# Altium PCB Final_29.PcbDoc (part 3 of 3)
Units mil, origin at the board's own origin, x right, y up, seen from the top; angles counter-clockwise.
Board outline 11000 x 6000 mil, 4 copper layers (TopLayer, MidLayer1, MidLayer2, BottomLayer), stack 29.222 mil thick; 209 components, 95 nets, 681 pads, 861 vias.
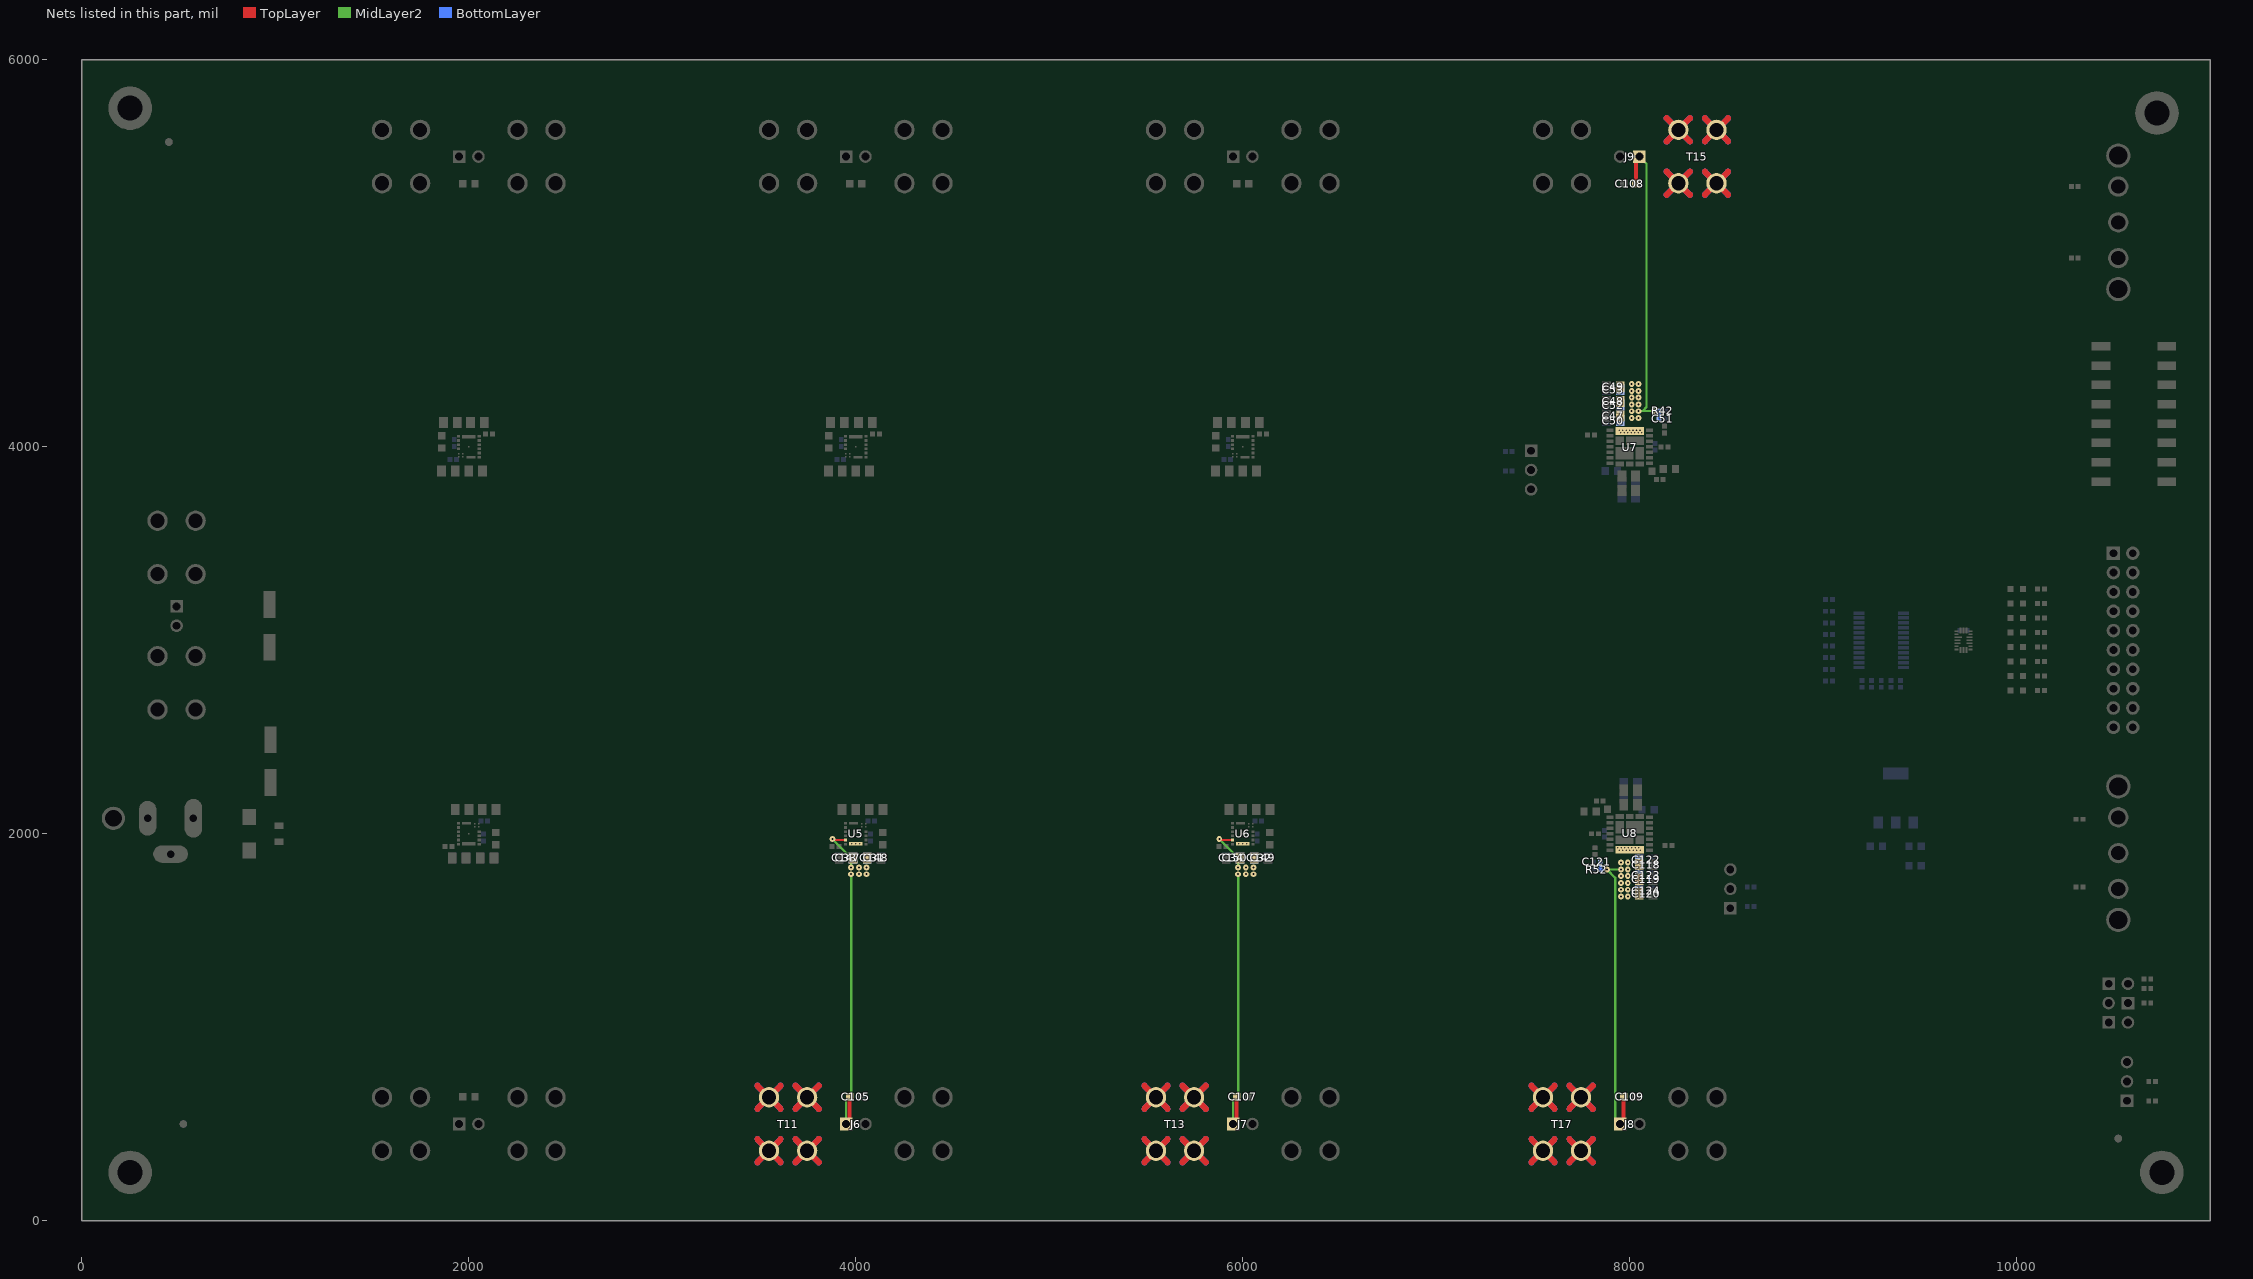
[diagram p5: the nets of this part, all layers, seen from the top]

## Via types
v1: diameter 30, hole 10, TopLayer to BottomLayer, tented both sides, 493 vias
v2: diameter 18, hole 8, TopLayer to BottomLayer, tented both sides, 308 vias
v3: diameter 18, hole 8, TopLayer to BottomLayer, tented bottom, 60 vias

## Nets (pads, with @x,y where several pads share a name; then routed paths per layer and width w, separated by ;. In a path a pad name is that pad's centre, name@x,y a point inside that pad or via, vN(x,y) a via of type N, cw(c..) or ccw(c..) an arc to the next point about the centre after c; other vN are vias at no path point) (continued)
VOUT5: C31.1 C33.1 C105.2 C147.1 C148.1 J6.1 T11.1 T11.2 T11.3 T11.4 U5.5 U5.7 | length 4417.6
  TopLayer w12: v1(3879,1973) 3884.5,1967.5 U5.5@3946.9,1967.5
  TopLayer w20: J6.1@3950,500 3968.5,518.5 C105.2@3968.5,640
  TopLayer w32: 3491.6,302.1 T11.2@3551.5,362 ; 3491.6,421.9 T11.2@3551.5,362 ; 3491.6,578.1 T11.1@3551.5,638 ; 3491.6,697.9 T11.1@3551.5,638 ; 3611.4,302.1 T11.2@3551.5,362 ; 3611.4,421.9 T11.2@3551.5,362 ; 3611.4,578.1 T11.1@3551.5,638 ; 3611.4,697.9 T11.1@3551.5,638 ; 3688.6,302.1 T11.3@3748.5,362 ; 3688.6,421.9 T11.3@3748.5,362 ; 3688.6,578.1 T11.4@3748.5,638 ; 3688.6,697.9 T11.4@3748.5,638 ; 3808.4,302.1 T11.3@3748.5,362 ; 3808.4,421.9 T11.3@3748.5,362 ; 3808.4,578.1 T11.4@3748.5,638 ; 3808.4,697.9 T11.4@3748.5,638
  MidLayer2 w12: v1(3879,1973) 3976,1876 v1(3976,1826) ; J6.1@3950,500 3950,618 3976,644 v1(3976,1791)
  BottomLayer w32: 3491.6,302.1 T11.2@3551.5,362 ; 3491.6,421.9 T11.2@3551.5,362 ; 3491.6,578.1 T11.1@3551.5,638 ; 3491.6,697.9 T11.1@3551.5,638 ; 3611.4,302.1 T11.2@3551.5,362 ; 3611.4,421.9 T11.2@3551.5,362 ; 3611.4,578.1 T11.1@3551.5,638 ; 3611.4,697.9 T11.1@3551.5,638 ; 3688.6,302.1 T11.3@3748.5,362 ; 3688.6,421.9 T11.3@3748.5,362 ; 3688.6,578.1 T11.4@3748.5,638 ; 3688.6,697.9 T11.4@3748.5,638 ; 3808.4,302.1 T11.3@3748.5,362 ; 3808.4,421.9 T11.3@3748.5,362 ; 3808.4,578.1 T11.4@3748.5,638 ; 3808.4,697.9 T11.4@3748.5,638
  other v1: 4016,1791 4056,1791 4016,1826 4056,1826
  other v2: 3979,1948 4000,1947.8 4021,1948
VOUT6: C32.1 C34.1 C107.2 C149.1 C150.1 J7.1 T13.1 T13.2 T13.3 T13.4 U6.5 U6.7 | length 4417.6
  TopLayer w12: v1(5879,1973) 5884.5,1967.5 U6.5@5946.9,1967.5
  TopLayer w20: J7.1@5950,500 5968.5,518.5 C107.2@5968.5,640
  TopLayer w32: 5491.6,302.1 T13.2@5551.5,362 ; 5491.6,421.9 T13.2@5551.5,362 ; 5491.6,578.1 T13.1@5551.5,638 ; 5491.6,697.9 T13.1@5551.5,638 ; 5611.4,302.1 T13.2@5551.5,362 ; 5611.4,421.9 T13.2@5551.5,362 ; 5611.4,578.1 T13.1@5551.5,638 ; 5611.4,697.9 T13.1@5551.5,638 ; 5688.6,302.1 T13.3@5748.5,362 ; 5688.6,421.9 T13.3@5748.5,362 ; 5688.6,578.1 T13.4@5748.5,638 ; 5688.6,697.9 T13.4@5748.5,638 ; 5808.4,302.1 T13.3@5748.5,362 ; 5808.4,421.9 T13.3@5748.5,362 ; 5808.4,578.1 T13.4@5748.5,638 ; 5808.4,697.9 T13.4@5748.5,638
  MidLayer2 w12: v1(5879,1973) 5976,1876 v1(5976,1826) ; J7.1@5950,500 5950,618 5976,644 v1(5976,1791)
  BottomLayer w32: 5491.6,302.1 T13.2@5551.5,362 ; 5491.6,421.9 T13.2@5551.5,362 ; 5491.6,578.1 T13.1@5551.5,638 ; 5491.6,697.9 T13.1@5551.5,638 ; 5611.4,302.1 T13.2@5551.5,362 ; 5611.4,421.9 T13.2@5551.5,362 ; 5611.4,578.1 T13.1@5551.5,638 ; 5611.4,697.9 T13.1@5551.5,638 ; 5688.6,302.1 T13.3@5748.5,362 ; 5688.6,421.9 T13.3@5748.5,362 ; 5688.6,578.1 T13.4@5748.5,638 ; 5688.6,697.9 T13.4@5748.5,638 ; 5808.4,302.1 T13.3@5748.5,362 ; 5808.4,421.9 T13.3@5748.5,362 ; 5808.4,578.1 T13.4@5748.5,638 ; 5808.4,697.9 T13.4@5748.5,638
  other v1: 6016,1791 6056,1791 6016,1826 6056,1826
  other v2: 5979,1948 6000,1947.8 6021,1948
VOUT7: C47.1 C48.1 C49.1 C50.1 C51.1 C52.1 C53.1 C108.2 J9.1 R42.1 T15.1 T15.2 T15.3 T15.4 U7.8 | length 4344.8
  TopLayer w20: C108.2@8031.5,5360 8031.5,5481.5 J9.1@8050,5500
  TopLayer w32: 8191.6,5302.1 T15.2@8251.5,5362 ; 8191.6,5421.9 T15.2@8251.5,5362 ; 8191.6,5578.1 T15.1@8251.5,5638 ; 8191.6,5697.9 T15.1@8251.5,5638 ; 8311.4,5302.1 T15.2@8251.5,5362 ; 8311.4,5421.9 T15.2@8251.5,5362 ; 8311.4,5578.1 T15.1@8251.5,5638 ; 8311.4,5697.9 T15.1@8251.5,5638 ; 8388.6,5302.1 T15.3@8448.5,5362 ; 8388.6,5421.9 T15.3@8448.5,5362 ; 8388.6,5578.1 T15.4@8448.5,5638 ; 8388.6,5697.9 T15.4@8448.5,5638 ; 8508.4,5302.1 T15.3@8448.5,5362 ; 8508.4,5421.9 T15.3@8448.5,5362 ; 8508.4,5578.1 T15.4@8448.5,5638 ; 8508.4,5697.9 T15.4@8448.5,5638
  MidLayer2 w12: v1(8045,4184) 8046,4185 8067,4185 ; J9.1@8050,5500 8087,5463 8087,4205 8067,4185 ; v1(8124,4185) 8067,4185
  BottomLayer w12: v1(8124,4185) R42.1@8152.3,4185 C51.1@8152.3,4145
  BottomLayer w32: 8191.6,5302.1 T15.2@8251.5,5362 ; 8191.6,5421.9 T15.2@8251.5,5362 ; 8191.6,5578.1 T15.1@8251.5,5638 ; 8191.6,5697.9 T15.1@8251.5,5638 ; 8311.4,5302.1 T15.2@8251.5,5362 ; 8311.4,5421.9 T15.2@8251.5,5362 ; 8311.4,5578.1 T15.1@8251.5,5638 ; 8311.4,5697.9 T15.1@8251.5,5638 ; 8388.6,5302.1 T15.3@8448.5,5362 ; 8388.6,5421.9 T15.3@8448.5,5362 ; 8388.6,5578.1 T15.4@8448.5,5638 ; 8388.6,5697.9 T15.4@8448.5,5638 ; 8508.4,5302.1 T15.3@8448.5,5362 ; 8508.4,5421.9 T15.3@8448.5,5362 ; 8508.4,5578.1 T15.4@8448.5,5638 ; 8508.4,5697.9 T15.4@8448.5,5638
  other v1: 8010,4149 8045,4149 8010,4184 8010,4219 8045,4219 8010,4254 8045,4254 8010,4289 8045,4289 8010,4324 8045,4324
  other v2: 7954,4073 7972,4073 7990,4073 8008,4073 8026,4073 8044,4073 8062,4073 7945,4086 7963,4086 7981,4086 7999,4086 8017,4086 8035,4086 8053,4086
VOUT8: C109.2 C118.1 C119.1 C120.1 C121.1 C122.1 C123.1 C124.1 J8.1 R52.1 T17.1 T17.2 T17.3 T17.4 U8.8 | length 4349.3
  TopLayer w20: J8.1@7950,500 7968.5,518.5 C109.2@7968.5,640
  TopLayer w32: 7491.6,302.1 T17.2@7551.5,362 ; 7491.6,421.9 T17.2@7551.5,362 ; 7491.6,578.1 T17.1@7551.5,638 ; 7491.6,697.9 T17.1@7551.5,638 ; 7611.4,302.1 T17.2@7551.5,362 ; 7611.4,421.9 T17.2@7551.5,362 ; 7611.4,578.1 T17.1@7551.5,638 ; 7611.4,697.9 T17.1@7551.5,638 ; 7688.6,302.1 T17.3@7748.5,362 ; 7688.6,421.9 T17.3@7748.5,362 ; 7688.6,578.1 T17.4@7748.5,638 ; 7688.6,697.9 T17.4@7748.5,638 ; 7808.4,302.1 T17.3@7748.5,362 ; 7808.4,421.9 T17.3@7748.5,362 ; 7808.4,578.1 T17.4@7748.5,638 ; 7808.4,697.9 T17.4@7748.5,638
  MidLayer2 w12: J8.1@7950,500 7925,525 7925,1772 v1(7882,1815) 7954,1815 v1(7955,1816)
  BottomLayer w12: C121.1@7847.7,1855 R52.1@7847.7,1815 v1(7882,1815)
  BottomLayer w32: 7491.6,302.1 T17.2@7551.5,362 ; 7491.6,421.9 T17.2@7551.5,362 ; 7491.6,578.1 T17.1@7551.5,638 ; 7491.6,697.9 T17.1@7551.5,638 ; 7611.4,302.1 T17.2@7551.5,362 ; 7611.4,421.9 T17.2@7551.5,362 ; 7611.4,578.1 T17.1@7551.5,638 ; 7611.4,697.9 T17.1@7551.5,638 ; 7688.6,302.1 T17.3@7748.5,362 ; 7688.6,421.9 T17.3@7748.5,362 ; 7688.6,578.1 T17.4@7748.5,638 ; 7688.6,697.9 T17.4@7748.5,638 ; 7808.4,302.1 T17.3@7748.5,362 ; 7808.4,421.9 T17.3@7748.5,362 ; 7808.4,578.1 T17.4@7748.5,638 ; 7808.4,697.9 T17.4@7748.5,638
  other v1: 7955,1676 7990,1676 7955,1711 7990,1711 7955,1746 7990,1746 7955,1781 7990,1781 7990,1816 7955,1851 7990,1851
  other v2: 7947,1914 7965,1914 7983,1914 8001,1914 8019,1914 8037,1914 8055,1914 7938,1927 7956,1927 7974,1927 7992,1927 8010,1927 8028,1927 8046,1927
pads on no net: J18.0 SW1.SH1 SW1.SH2 SW2.SH1 SW2.SH2 U1.15 U2.15 U3.15 U4.15 U5.15 U6.15 U7.1 U8.1
copper on no net: | length 93.2
  TopLayer w12: 7885,2127 7897.6,2114.4 7897.6,2085.6 ; 8102.4,3914.4 8102.4,3885.6 8115,3873

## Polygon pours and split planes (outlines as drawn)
3.3V on TopLayer "3.3V_1" (solid, remove dead copper, pour order 95): 77 vertices, not listed, extent 8840,917 10737,3540
N1133411 on TopLayer "N1133411_1" (solid, remove dead copper, pour order 88): 8208,2108 8178,2078 8091,2078 8091,2091 8153,2153 8208,2153
N983153 on TopLayer "N983153_1" (solid, remove dead copper, pour order 76): 7983,3895 7983,3922 8018,3922 8018,3895
N983255 on TopLayer "N983255_1" (solid, remove dead copper, pour order 77): 7792,3892 7822,3922 7909,3922 7909,3909 7847,3847 7792,3847
PGND on TopLayer "PGND_1" (solid, remove dead copper, pour order 87): 10614.7,1190.3 ccw(c10574.96,1224.93) 10624.6,1207.2 10625.8,1210.5 10634.3,1210.5 10634.3,1187.2 ccw(c10644.49,1187.25) 10634.8,1184.1 cw(c10625.29,1181) 10625.3,1171 10622.5,1171 10621.1,1172.3 ccw(c10607.64,1157.39) 10617.3,1175 cw(c10622.22,1183.71)
PGND on TopLayer "PGND_2" (solid, remove dead copper, pour order 64): 95 vertices, not listed, extent 54,51 1955.6,5947
PGND on TopLayer "PGND_3" (solid, remove dead copper, pour order 112): 69 vertices, not listed, extent 2013,53 3953,2336
PGND on TopLayer "PGND_4" (solid, remove dead copper, pour order 66): 67 vertices, not listed, extent 4014,3664 5955.7,5948
PGND on TopLayer "PGND_5" (solid, remove dead copper, pour order 86): 176 vertices, not listed, extent 7982,52 10948,2792
PGND on TopLayer "PGND_6" (solid, remove dead copper, pour order 85): 10620.7,1277.9 10660.5,1277.9 cw(c10660.43,1267.91) 10670.1,1265.4 ccw(c10679.92,1262.95) 10669.8,1262.8 10669.8,1237.2 ccw(c10679.91,1237.1) 10670,1235.1 cw(c10660.23,1232.99) 10660.2,1223 10644.5,1223 ccw(c10644.61,1212.82) 10640.9,1222.3 cw(c10637.35,1231.66) 10627.4,1230.6 ccw(c10575,1225.01) 10613.4,1261.1 cw(c10620.73,1267.9)
PGND on TopLayer "PGND_7" (solid, remove dead copper, pour order 84): 10616.5,872 10697.6,872 10697.6,743 10669.5,743 ccw(c10669.5,732.85) 10661,738.4 10659.5,736.1 10620.3,736.1 10619,739.3 ccw(c10569.97,720.02) 10601.8,762 cw(c10607.83,770) 10601.8,778 ccw(c10570.05,820) 10622.7,820 ccw(c10570.09,820) 10609.1,855.3 cw(c10616.53,862)
PGND on TopLayer "PGND_8" (solid, remove dead copper, pour order 98): 66 vertices, not listed, extent 2014,3664 3955.7,5948
PGND on TopLayer "PGND_9" (solid, remove dead copper, pour order 99): 96 vertices, not listed, extent 6014,3664 8018,5948
PGND on TopLayer "PGND_10" (solid, remove dead copper, pour order 100): 71 vertices, not listed, extent 4013,53 5953,2336
PGND on TopLayer "PGND_11" (solid, remove dead copper, pour order 101): 46 vertices, not listed, extent 6013,53 7782,2336
PGND on TopLayer "PGND_12" (solid, remove dead copper, pour order 103): 49 vertices, not listed, extent 8218,3340 10948,5949
PVIN on TopLayer "PVIN_1" (solid, remove dead copper, pour order 96): 212 vertices, not listed, extent 264,1788 9280,3999
VOUT1 on TopLayer "VOUT1_1" (solid, remove dead copper, pour order 97): 18 vertices, not listed, extent 1015,4043.4 2038,5948
VOUT2 on TopLayer "VOUT2_1" (solid, remove dead copper, pour order 108): 18 vertices, not listed, extent 3015,4043.4 4038,5948
VOUT3 on TopLayer "VOUT3_1" (solid, remove dead copper, pour order 109): 18 vertices, not listed, extent 5015,4043.4 6038,5948
VOUT4 on TopLayer "VOUT4_1" (solid, remove dead copper, pour order 65): 19 vertices, not listed, extent 1058,52 2087,1956.6
VOUT5 on TopLayer "VOUT5_1" (solid, remove dead copper, pour order 110): 19 vertices, not listed, extent 3015,52 4087,1956.6
VOUT6 on TopLayer "VOUT6_1" (solid, remove dead copper, pour order 111): 19 vertices, not listed, extent 5015,52 6087,1956.6
VOUT7 on TopLayer "VOUT7_1" (solid, remove dead copper, pour order 102): 19 vertices, not listed, extent 7926.2,4062 8810,5948
VOUT8 on TopLayer "VOUT8_1" (solid, remove dead copper, pour order 104): 34 vertices, not listed, extent 7015,52 8073.8,1937
3.3V on BottomLayer "3.3V_2" (solid, remove dead copper, pour order 94): 9487,2009 9440,2009 9440,2093 9627,2093 9627,1813 9487,1813
N1133327 on BottomLayer "N1133327_1" (solid, remove dead copper, pour order 83): 8021,2077 8019,2075 7982,2075 7982,2145 8081,2145 8081,2106 8021,2106
N1133411 on BottomLayer "N1133411_2" (solid, remove dead copper, pour order 89): 8193,2085 8106,2085 8106,2145 8193,2145
N983153 on BottomLayer "N983153_2" (solid, remove dead copper, pour order 78): 7979,3923 7981,3925 8018,3925 8018,3855 7919,3855 7919,3894 7979,3894
N983255 on BottomLayer "N983255_2" (solid, remove dead copper, pour order 82): 7805,3915 7894,3915 7894,3855 7805,3855
PGND on BottomLayer "PGND_14" (solid, remove dead copper, pour order 121): 9711.3,3103.9 9858.3,3103.9 9864.8,3097.4 9864.8,3095.3 ccw(c9890.01,3094.97) 9876.8,3073.5 cw(c9871.59,3065) 9876.8,3056.5 ccw(c9890.04,3035.06) 9865.2,3039.3 9864.5,3035.1 9730.2,3035.1 9730.2,3062.8 ccw(c9720.1,3062.8) 9720.1,3072.9 9708.9,3072.9 9704.2,3077.6 9704.2,3079.7 ccw(c9678.97,3080.15) 9702.2,3090 cw(c9711.37,3093.92)
PGND on BottomLayer "PGND_15" (solid, remove dead copper, pour order 120): 9596.2,2938.4 9843.8,2938.4 9864.8,2917.4 9864.8,2915.3 ccw(c9890.02,2914.79) 9865.4,2909.3 cw(c9855.67,2907.08) 9855.7,2897.1 9575.1,2897.1 cw(c9575.07,2907.1) 9565.1,2907.9 ccw(c9540.01,2910.15) 9565.2,2910 ccw(c9540.03,2909.61) 9565,2912.8 cw(c9574.95,2913.89) 9575,2923.9 ccw(c9575,2940.08) 9586.4,2928.6
PGND on BottomLayer "PGND_16" (solid, remove dead copper, pour order 119): 224 vertices, not listed, extent 51,50 10950,5949
PVIN on BottomLayer "PVIN_2" (solid, remove dead copper, pour order 67): 5978,2240 6092,2240 6092,2092 6074,2092 6074,2026 6029,2026 6022,2033 6022,2079 5978,2079
PVIN on BottomLayer "PVIN_3" (solid, remove dead copper, pour order 68): 1978,2240 2092,2240 2092,2092 2074,2092 2074,2026 2022,2026 2022,2079 1978,2079
PVIN on BottomLayer "PVIN_4" (solid, remove dead copper, pour order 69): 3978,2240 4092,2240 4092,2092 4074,2092 4074,2026 4022,2026 4022,2079 3978,2079
PVIN on BottomLayer "PVIN_5" (solid, remove dead copper, pour order 70): 6022,3760 5908,3760 5908,3908 5926,3908 5926,3974 5974,3974 5978,3970 5978,3921 6022,3921
PVIN on BottomLayer "PVIN_6" (solid, remove dead copper, pour order 71): 4022,3760 3908,3760 3908,3908 3926,3908 3926,3974 3978,3974 3978,3921 4022,3921
PVIN on BottomLayer "PVIN_7" (solid, remove dead copper, pour order 75): 2022,3760 1908,3760 1908,3908 1926,3908 1926,3974 1978,3974 1978,3921 2022,3921
PVIN on BottomLayer "PVIN_8" (solid, remove dead copper, pour order 91): 7850,2316 7993,2316 7993,2150.1 7976.9,2150.1 7976.9,2150 7968,2150 7968,1990 7892.9,1990 7892.9,2005.2 7887.9,2005.2 7887.9,2035.6 7874.9,2035.6 7866.7,2043.8 7857.1,2043.8 ccw(c7837.71,2027.69) 7850,2049.7
PVIN on BottomLayer "PVIN_9" (solid, remove dead copper, pour order 80): 8083.1,4015 8112.1,4015 8112.1,3964.4 8125.1,3964.4 8133.3,3956.2 8142.9,3956.2 ccw(c8162.29,3972.31) 8150,3950.3 8150,3684 8007,3684 8007,3844 8032,3844 8032,4014.9 8083.1,4014.9
PVIN on BottomLayer "PVIN_10" (solid, remove dead copper, pour order 93): 9263,1862 9126,1862 9126,2092 9310,2092 9310,2014 9263,2014
VOUT1 on BottomLayer "VOUT1_2" (solid, remove dead copper, pour order 115): 17 vertices, not listed, extent 1015,4043 2039,5948
VOUT2 on BottomLayer "VOUT2_2" (solid, remove dead copper, pour order 116): 3849,5311 3986,5311 3986,5010 4039,5010 4039,4056 4026,4043 3975,4043 3921,4097 3917,4097 3917,4315 3015,4315 3015,5948 3986,5948 3986,5616 3849,5616
VOUT3 on BottomLayer "VOUT3_2" (solid, remove dead copper, pour order 117): 17 vertices, not listed, extent 5015,4043 6039,5948
VOUT4 on BottomLayer "VOUT4_2" (solid, remove dead copper, pour order 113): 17 vertices, not listed, extent 1058,52 2088,1957
VOUT5 on BottomLayer "VOUT5_2" (solid, remove dead copper, pour order 72): 17 vertices, not listed, extent 3015,52 4088,1957
VOUT6 on BottomLayer "VOUT6_2" (solid, remove dead copper, pour order 73): 6029,1957 6088,1898 6088,988 5986,988 5986,695 5860,695 5860,410 5984,410 5984,52 5015,52 5015,1711 5960,1711 5960,1943 5974,1957
VOUT7 on BottomLayer "VOUT7_2" (solid, remove dead copper, pour order 118): 22 vertices, not listed, extent 7928,4063 8810,5948
VOUT8 on BottomLayer "VOUT8_2" (solid, remove dead copper, pour order 114): 29 vertices, not listed, extent 7015,52 8072,1937
AGND1 on BottomLayer "AGND1_1" (solid, remove dead copper, pour order 79): 8000,4020 8000,4042 8078,4042 8078,4020
AGND2 on BottomLayer "AGND2_1" (solid, remove dead copper, pour order 92): 8000,1980 8000,1958 7922,1958 7922,1980
PGND on MidLayer2 "PGND_26" (solid, remove dead copper, pour order 122): 50,50 50,5950 10950,5950 10950,50
PGND on MidLayer2 "PGND_17" (solid, remove dead copper, pour order 131): 21 vertices, not listed, extent 9564.97,3201.2 10448.6,3281.9
PGND on MidLayer2 "PGND_18" (solid, remove dead copper, pour order 130): 19 vertices, not listed, extent 9898.44,3021.1 10468.17,3133.9
PGND on MidLayer2 "PGND_19" (solid, remove dead copper, pour order 129): 23 vertices, not listed, extent 9548.44,3021.1 9881.56,3109.9
PGND on MidLayer2 "PGND_20" (solid, remove dead copper, pour order 128): 18 vertices, not listed, extent 9898.44,2871.06 10468.17,2988.9
PGND on MidLayer2 "PGND_21" (solid, remove dead copper, pour order 127): 9574.1,2988.9 9855,2988.9 cw(c9855.05,2978.89) 9865,2977.8 ccw(c9889.97,2974.61) 9864.8,2975 ccw(c9890.06,2975) 9876.8,2953.5 cw(c9871.59,2945) 9876.8,2936.5 ccw(c9890.06,2915) 9864.8,2915 ccw(c9889.99,2915.15) 9864.9,2912.9 cw(c9854.93,2912.1) 9854.9,2902.1 9630.7,2902.1 9565.2,2967.6 9565.2,2969.7 ccw(c9539.99,2970.09) 9564.4,2976.4 cw(c9574.07,2978.91)
PGND on MidLayer2 "PGND_22" (solid, remove dead copper, pour order 126): 23 vertices, not listed, extent 9565.2,2725.94 10447.95,2857
PGND on MidLayer2 "PGND_23" (solid, remove dead copper, pour order 125): 10041,2838.9 10445.8,2838.9 10446.8,2835.2 ccw(c10499.95,2850.1) 10455.7,2817.1 cw(c10447.69,2811.1) 10447.7,2801.1 10054.7,2801.1 10033.9,2821.8 cw(c10040.98,2828.88)
PGND on MidLayer2 "PGND_24" (solid, remove dead copper, pour order 124): 22 vertices, not listed, extent 8301.7,636.1 10542.15,2014.9
PGND on MidLayer2 "PGND_25" (solid, remove dead copper, pour order 123): 18 vertices, not listed, extent 9914.1,3142.1 10468.17,3210.9
VOUT1 on MidLayer2 "VOUT1_3" (solid, remove dead copper, pour order 74): 1968,4181.7 1968,4201.3 1968.2,4202 ccw(c1944,4209.03) 1969.2,4209 ccw(c1944,4208.97) 1968.2,4216 1968,4216.7 1968,4225 2041,4225 2041,4156 1968,4156 1968,4166.3 1968.2,4167 ccw(c1944,4174.03) 1969.2,4174 ccw(c1944,4173.97) 1968.2,4181
VOUT2 on MidLayer2 "VOUT2_3" (solid, remove dead copper, pour order 61): 3968,4181.7 3968,4201.3 3968.2,4202 ccw(c3944,4209.03) 3969.2,4209 ccw(c3944,4208.97) 3968.2,4216 3968,4216.7 3968,4225 4041,4225 4041,4156 3968,4156 3968,4166.3 3968.2,4167 ccw(c3944,4174.03) 3969.2,4174 ccw(c3944,4173.97) 3968.2,4181
VOUT3 on MidLayer2 "VOUT3_3" (solid, remove dead copper, pour order 63): 5968,4181.7 5968,4201.3 5968.2,4202 ccw(c5944,4209.03) 5969.2,4209 ccw(c5944,4208.97) 5968.2,4216 5968,4216.7 5968,4225 6041,4225 6041,4156 5968,4156 5968,4166.3 5968.2,4167 ccw(c5944,4174.03) 5969.2,4174 ccw(c5944,4173.97) 5968.2,4181
VOUT4 on MidLayer2 "VOUT4_3" (solid, remove dead copper, pour order 62): 2032,1818.3 2032,1798.7 2031.8,1798 ccw(c2056,1790.97) 2030.8,1791 ccw(c2056,1791.03) 2031.8,1784 2032,1783.3 2032,1775 1959,1775 1959,1844 2032,1844 2032,1833.7 2031.8,1833 ccw(c2056,1825.97) 2030.8,1826 ccw(c2056,1826.03) 2031.8,1819
VOUT5 on MidLayer2 "VOUT5_3" (solid, remove dead copper, pour order 60): 4032,1818.3 4032,1798.7 4031.8,1798 ccw(c4056,1790.97) 4030.8,1791 ccw(c4056,1791.03) 4031.8,1784 4032,1783.3 4032,1775 3959,1775 3959,1844 4032,1844 4032,1833.7 4031.8,1833 ccw(c4056,1825.97) 4030.8,1826 ccw(c4056,1826.03) 4031.8,1819
VOUT6 on MidLayer2 "VOUT6_3" (solid, remove dead copper, pour order 59): 6032,1818.3 6032,1798.7 6031.8,1798 ccw(c6056,1790.97) 6030.8,1791 ccw(c6056,1791.03) 6031.8,1784 6032,1783.3 6032,1775 5959,1775 5959,1844 6032,1844 6032,1833.7 6031.8,1833 ccw(c6056,1825.97) 6030.8,1826 ccw(c6056,1826.03) 6031.8,1819
AGND1 on MidLayer2 "AGND1_2" (solid, remove dead copper, pour order 81): 77 vertices, not listed, extent 7266,3696 8337,4379
AGND2 on MidLayer2 "AGND2_2" (solid, remove dead copper, pour order 90): 92 vertices, not listed, extent 7663,1581 8719,1983
PGND on MidLayer1 "PGND_13" (solid, remove dead copper, pour order 107): 51,5949 10948,5949 10948,52 51,52

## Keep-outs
TopLayer:
  region: 10479,425 ccw(c10525,425) 10571,425 ccw(c10525,425)
  region: 479,500 ccw(c525,500) 571,500 ccw(c525,500)
  region: 404,5575 ccw(c450,5575) 496,5575 ccw(c450,5575)
BottomLayer:
  region: 10571,425 cw(c10525,425) 10479,425 cw(c10525,425)
  region: 571,500 cw(c525,500) 479,500 cw(c525,500)
  region: 496,5575 cw(c450,5575) 404,5575 cw(c450,5575)
KeepOutLayer:
  region: 117.6,250 ccw(c250,250) 382.4,250 ccw(c250,250)
  region: 117.6,5750 ccw(c250,5750) 382.4,5750 ccw(c250,5750)
  region: 10617.6,250 ccw(c10750,250) 10882.4,250 ccw(c10750,250)
  region: 10592.6,5725 ccw(c10725,5725) 10857.4,5725 ccw(c10725,5725)
  region: 10515,1200 10515,1150 10535,1150 10535,1200
  region: 10550,2925 10550,2885 10560,2885 10560,2925
  region: 10545,3025 10545,2985 10565,2985 10565,3025

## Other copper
TopLayer:
  text "COMPONENT-SIDE" at 3394,-675 h73.5
  text "1" at 6569,-675 h73.5
MidLayer1:
  rectangle net AGND2: 7926,1947 8005,1985
  rectangle net AGND1: 7997,4017 8079,4053
  region net PGND: 7864,1909 7885,1928 7926,1960 7931,1949 7894,1905 7873,1896
  region net PGND: 8127,4102 8108,4095 8072,4052 8078.83,4041.7 8136,4090
  text "2" at 6569,-675 h73.5
  text "GROUND PLANE" at 3420.5,-679.5 h73.5
MidLayer2:
  text "3" at 5891.5,-654.5 h73.5
  text "3" at 6591.5,-654.5 h73.5
  text "INTERNAL SIGNAL" at 3420.5,-679.5 h73.5
BottomLayer:
  text "SOLDER-SIDE" at 3394,-675 h73.5
  text "4" at 6569,-675 h73.5

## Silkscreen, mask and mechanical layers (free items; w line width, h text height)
TopOverlay:
  region: 6145,2955 6145,2770 8375,2770 8375,2955
  region: 7960,3250 7960,3045 8375,3045 8375,3250
  lines w8: 1705,4325 1815,4325 ; 1785,4295 1815,4325 ; 1785,4350 1810,4325 1815,4325 ; 1815,3980 1815,3825 2130,3825 2130,3955 ; 1815,4070 1815,4175 1855,4175 ; 1815,4200 1815,4370 ; 1865,1895 1865,1815 2195,1815 2195,1935 ; 1865,2070 1865,2180 1885,2180 ; 2100,4175 2130,4175 2130,4110 ; 2130,4190 2130,4370 ; 2145,3825 2430,3825 ; 2155,4175 2430,4175 ; 2160,4295 2135,4320 2130,4320 ; 2160,4350 2130,4320 ; 2190,2180 2195,2180 2195,2030 ; 2240,4320 2130,4320 ; 2335,3860 2365,3830 2365,3825 ; 2335,4145 2360,4170 2360,4175 ; 2360,4065 2360,4175 ; 2365,3980 2365,3825 ; 2390,4145 2360,4175 ; 2400,3860 2365,3825 ; 3815,3980 3815,3825 4130,3825 4130,3955 ; 3815,4070 3815,4175 3830,4175 ; 3865,1895 3865,1815 4195,1815 4195,1935 ; 3865,2070 3865,2180 3885,2180 ; 4120,4175 4130,4175 4130,4110 ; 4190,2180 4195,2180 4195,2030 ; 5815,3980 5815,3825 6130,3825 6130,3955 ; 5815,4070 5815,4175 5835,4175 ; 5865,1895 5865,1815 6195,1815 6195,1935 ; 5865,2070 5865,2180 5885,2180 ; 6130,4110 6130,4180 ; 6190,2180 6195,2180 6195,2030 ; 7635,4530 7745,4530 ; 7715,4500 7745,4530 ; 7715,4555 7740,4530 7745,4530 ; 7745,1853 7745,1650 8280,1650 ; 7745,2164 7745,2305 8280,2305 8280,2002 ; 7745,3960 7745,3710 8280,3710 8280,3760 ; 7745,4345 7745,4365 8280,4365 8280,4145 ; 7745,4380 7745,4565 ; 8280,4385 8280,4565 ; 8290,4365 8605,4365 ; 8295,3710 8605,3710 8605,3705 ; 8315,4505 8290,4530 8285,4530 ; 8315,4560 8285,4530 ; 8395,4530 8285,4530 ; 8470,3745 8500,3715 ; 8475,4330 8500,4355 8500,4360 ; 8500,3960 8500,3715 ; 8500,4100 8500,4360 ; 8525,3745 8500,3720 8500,3715 ; 8530,4330 8500,4360
  text "GND" at 10724.87,5323.3 h49
  text "VOUT7" at 8156.08,5158 h78.4
  text "PGND" at 2194.07,5153 h78.4
  text "PGND" at 4194.07,5153 h78.4
  text "PGND" at 6194.07,5153 h78.4
  text "VOUT1" at 1441.08,5148 h78.4
  text "VOUT2" at 3441.08,5148 h78.4
  text "VOUT3" at 5441.08,5148 h78.4
  text "PGND" at 7499.07,5143 h78.4
  text "3.3V" at 10717.34,4963.3 h49
  text "13.5mm" at 7917.28,4510 h49
  text "EN1" at 10184.87,4495 h49
  text "EN2" at 10184.87,4395 h49
  text "8mm" at 1919.87,4305 h49
  text "EN3" at 10184.87,4295 h49
  text "EN4" at 10184.87,4195 h49
  text "EN5" at 10184.87,4095 h49
  text "16.6mm" at 8497.28,4025 h49
  text "8.9mm" at 2324.81,4000 h49
  text "EN6" at 10184.87,3995 h49
  text "SYNC" at 7265.34,3959 h49
  text "EN7" at 10184.87,3895 h49
  text "SALERT" at 7198.28,3852 h49
  text "EN8" at 10184.87,3795 h49
  text "PVIN" at 650.07,3449 h78.4
  text "POWER MICRO BOARD REV" at 5952.86,3075 h98
  text "S/N" at 5780.07,2811.7 h98
  text "uPOL" at 4372.67,2805 h196
  text "PGND" at 658.07,2730 h78.4
  text "GND" at 10739.87,2063.3 h49
  text "3.3V" at 10732.34,1703.3 h49
  text "SALERT" at 8636.28,1696 h49
  text "SYNC" at 8614.34,1591 h49
  text "GND" at 10379.87,800 h49
  text "PGND" at 2172.07,757 h78.4
  text "PGND" at 4172.07,757 h78.4
  text "PGND" at 6172.07,757 h78.4
  text "PGND" at 8172.07,757 h78.4
  text "VOUT4" at 1419.08,752 h78.4
  text "VOUT5" at 3419.08,752 h78.4
  text "VOUT6" at 5419.08,752 h78.4
  text "VOUT8" at 7419.08,752 h78.4
  text "SDA" at 10380.87,698 h49
  text "SCL" at 10382.87,586 h49
  text "SILKSCREEN C.S." at 3294,-675 h73.5
  text "7" at 6569,-675 h73.5
BottomOverlay:
  text "SILKSCREEN S.S." at 3294,-675 h73.5
  text "8" at 6569,-675 h73.5
TopPaste:
  drawing of 76 lines, arcs and shapes, not listed
  text "SOLDER PASTE C.S." at 3294,-675 h73.5
  text "9" at 6569,-675 h73.5
BottomPaste:
  text "SOLDER PASTE S.S." at 3294,-675 h73.5
  text "10" at 6569,-675 h73.5
TopSolder:
  drawing of 114 lines, arcs and shapes, not listed
  text "SOLDER MASK C.S." at 3394,-675 h73.5
  text "5" at 6569,-675 h73.5
BottomSolder:
  drawing of 171 lines, arcs and shapes, not listed
  text "SOLDER MASK S.S." at 3394,-675 h73.5
  text "6" at 6569,-675 h73.5
Board_Outline:
  drawing of 172 lines, arcs and shapes, not listed
  text "5" at -6010.08,10706 h122.5
  text "4" at -2045.08,10706 h122.5
  text "3" at 1919.92,10706 h122.5
  text "2" at 5884.92,10706 h122.5
  text "1" at 9849.92,10706 h122.5
  text "REVISIONS" at 8575,10490 h122.5
  text "LTR" at 6263,10240 h98
  text "DESCRIPTION" at 7625,10240 h98
  text "BY" at 9828,10240 h98
  text "DATE" at 10255,10240 h98
  text "APPROVED" at 10850,10240 h98
  text "C" at -8068.08,7805 h122.5
  text "B" at -8068.08,2680 h122.5
  text "UNLESS OTHERWISE SPECIFIED" at 1775,-2185 h98
  text "CONTRACT NO." at 4513.96,-2210 h98
  text "DIMENSIONS ARE IN INCHES" at 1850,-2360 h98
  text "A" at -8068.08,-2420 h122.5
  text "TOLERANCES ON" at 2525,-2610 h98
  text "SIGNATURE" at 4737.67,-2835 h98
  text "TITLE" at 6877.6,-2835 h98
  text "2 PLACES DECIMALS" at 1775,-2860 h98
  text "+.02" at 3553.83,-2870 h98
  text "3 PLACES DECIMALS" at 1775,-3110 h98
  text "+.005" at 3562.6,-3120 h98
  text "+" at 4106.92,-3120 h122.5
  text "PREPARED" at 4425,-3185 h78.4
  text "POWER MICROSTRIP GEN 1" at 7170,-3230 h196
  text "+" at 4175,-3310 h92.12
  text "+1" at 3575,-3335 h92.12
  text "ANGLES" at 1750,-3360 h98
  text "CHECKED" at 4425,-3485 h78.4
  text "DO NOT SCALE THIS DRAWING" at 1825,-3610 h98
  text "ENGINEER" at 4425,-3785 h78.4
  text "MATERIAL" at 1750,-3885 h98
  text "SIZE" at 6868.83,-4035 h98
  text "DRAWING NO." at 7405.2,-4035 h98
  text "REV." at 11293.83,-4035 h98
  text "Q.A." at 4425,-4060 h78.4
  text "PROGRAM" at 4450,-4235 h78.4
  text "MANG." at 4450,-4335 h78.4
  text "C" at 6930.68,-4404 h171.5
  text "NEXT ASSY" at -925,-4460 h98
  text "USED ON" at 625,-4460 h98
  text "FINAL PROTECTIVE FINISH" at 1750,-4460 h98
  text "RELEASE" at 4500,-4610 h78.4
  text "APPLICATION" at -250,-4735 h98
  text "SCALE" at 6877.6,-4735 h98
  text "SHEET" at 9852.6,-4735 h98
  text "OF" at 11126.3,-4735 h98
  text "1" at 11417.53,-4735 h98
  text "DATE" at 4500,-4760 h78.4
PLACE_BOUND_TOP:
  region: 10613,5725 ccw(c10725,5725) 10837,5725 ccw(c10725,5725)
  region: 10638,250 ccw(c10750,250) 10862,250 ccw(c10750,250)
  region: 138,250 ccw(c250,250) 362,250 ccw(c250,250)
  region: 138,5750 ccw(c250,5750) 362,5750 ccw(c250,5750)
DB36:
  drawing of 640 lines, arcs and shapes, not listed
  text "FARADAY SEMI" at 2425,-350 h73.5
  text "PWB." at 4469,-350 h73.5
  text "POWERSTRIP" at 4844,-350 h73.5
  text "DATE:" at 6094,-350 h73.5
  text "10/29/20" at 6569,-350 h73.5
  text "LAYER NAME:" at 2419,-675 h73.5
  text "LAYER NO." at 5094,-675 h73.5
  text "FILM" at 6169,-675 h73.5
  text "OF" at 6794,-675 h73.5
  text "10" at 6994,-675 h73.5
  text "LARGO" at 3943,-1101.2 h98
  text "CIRCUIT" at 4618,-1101.2 h98
  text "DESIGN" at 5463,-1101.2 h98
  text "WWW.LARGO-CD.COM" at 5015,-1229.2 h61.74
  text "(714)898-1588" at 3939,-1230.2 h61.74
  text "DRW.POWERSTRIP" at 5015,-1379.2 h61.74
  text "PROJ.PCB.3579" at 3939,-1380.2 h61.74
  text "LARGO" at 5015,-1504.2 h61.74
  text "REV.01" at 5415,-1504.2 h61.74
  text "C.S.-VIEW" at 3989,-1535.2 h78.4
SPLIT:
  lines w25: 975,1725 2000,1725 ; 1000,3475 1000,6125 ; 1475,2350 11200,2350 ; 1475,3000 11200,3000 ; 1600,3650 8300,3650 ; 2000,375 2000,975 2100,975 2100,1050 ; 2000,5265 2000,5935 ; 2975,1725 4000,1725 ; 3000,-700 3000,4450 ; 3001,5282 3001,5952 ; 4000,5265 4000,5935 ; 5000,-225 5000,4375 ; 5001,5282 5001,5952 ; 6000,5265 6000,5935 ; 6925,1900 7875,1900 ; 7000,-250 7000,3725 ; 7000,3475 7000,6125 ; 7915,4116 7915,5026 8000,5025 8000,6075 ; 8000.5,-81.5 8000.5,968.5 8085.5,967.5 8085.5,1877.5 ; 8075,4125 8824,4125 8826,6072 ; 8150,3800 8825,3800 8825,2350 ; 8525,2175 9050,2175 9050,1775 10100,1775 10100,825 10750,825 10750,1450 ; 8850,3325 10150,3325 10150,3550 10225,3550 10225,5150 10300,5150 10300,5625 11025,5625
PLACE_GRID_TOP:
  lines w0.04: -550,2000 11800,2000 ; -450,4000 10500,4000 ; 2000,-1000 2000,9600 ; 4000,-1000 4000,9600 ; 6000,-700 6000,9900 ; 8000,-1000 8000,9600
DIMENSION:
  lines w0.04: -1243,0 -100,0 ; -1050,0 -100,0 ; -1050,6000 -100,6000 ; -950,3418 -950,0 ; -950,3932 -950,6000 ; -550,0 -100,0 ; -550,250 150,250 ; -450,-300 -450,0 ; -450,1468 -450,250 ; -300,-300 0,-300 ; 0,-1043 0,-100 ; 0,-825 0,-100 ; 0,-400 0,-100 ; 250,-400 250,150 ; 718,-300 250,-300 ; 990,6475 1210,6475 1891.1,4090 ; 2645,6475 2925,6475 3905,4090 ; 3760,-1125 3405,-1125 2111.7,1900 ; 4715,6480 4945,6480 5897,4090 ; 4968,-725 0,-725 ; 5240,-1145 4820,-1140 4101.1,1900 ; 6432,-725 11000,-725 ; 7915,-1185 7540,-1170 6077.4,1900 ; 9055,6480 8605,6475 8100,4106.2 ; 9805,-1175 9360,-1175 8052.2,1885 ; 11000,-825 11000,-100 ; -7280,-3420 -7230,-3570 ; -7280,-3420 -7180,-3420 ; -7280,-3420 -7230,-3570 ; -7280,-3420 -7180,-3420 ; -7280,-2470 -7230,-2320 ; -7280,-2470 -7180,-2470 ; -7280,-2470 -7230,-2320 ; -7280,-2470 -7180,-2470 ; -7230,-3570 -7180,-3420 ; -7230,-3570 -7230,-3270 -7230,-3570 ; -7230,-3570 -7180,-3420 ; -7230,-2320 -7230,-2645 -7230,-2320 ; -7230,-2320 -7180,-2470 ; -7230,-2320 -7180,-2470 ; -950,0 -975,150 -925,150 -950,0 ; -950,6000 -925,5850 -975,5850 -950,6000 ; -450,0 -425,-150 -475,-150 -450,0 ; -450,250 -475,400 -425,400 -450,250 ; 0,-725 150,-700 150,-750 0,-725 ; 0,-300 -150,-325 -150,-275 0,-300 ; 250,-300 400,-275 400,-325 250,-300 ; 1891.1,4090 1825.9,4227.4 1873.9,4241.1 1891.1,4090 ; 2111.7,1900 2193.7,1771.9 2147.7,1752.2 2111.7,1900 ; 3905,4090 3824.9,4219.2 3871.1,4238.2 3905,4090 ; 4101.1,1900 4159.9,1759.8 4111.3,1748.3 4101.1,1900 ; 5897,4090 5818.3,4220.1 5864.7,4238.6 5897,4090 ; 6077.4,1900 6164.5,1775.3 6119.3,1753.8 6077.4,1900 ; 8052.2,1885 8134.1,1756.9 8088.2,1737.2 8052.2,1885 ; 8100,4106.2 8106.8,4258.1 8155.7,4247.7 8100,4106.2 ; 11000,-725 10850,-750 10850,-700 11000,-725 ; -7765,4865 -7470,4865 -7470,5120 -7765,5120 -7765,4865 ; -7760.5,4290.5 -7465.5,4290.5 -7465.5,4545.5 -7760.5,4545.5 -7760.5,4290.5 ; -7730,-3570 -6580,-3570 -7730,-3570 ; -7730,-2320 -6580,-2320 -7730,-2320 ; 0,0 11000,0 11000,6000 0,6000 0,0 ; 1865,3880 2060,3880 2060,4090 1865,4090 1865,3880 ; 1940,1900 2135,1900 2135,2125 1940,2125 1940,1900 ; 3865,3880 4060,3880 4060,4090 3865,4090 3865,3880 ; 3940,1900 4135,1900 4135,2125 3940,2125 3940,1900 ; 5865,3880 6060,3880 6060,4090 5865,4090 5865,3880 ; 5940,1900 6135,1900 6135,2125 5940,2125 5940,1900 ; 7785,3845 8100,3845 8100,4110 7785,4110 7785,3845 ; 7880,1885 8205,1885 8205,2145 7880,2145 7880,1885
  text "18" at 802.22,6437.5 h73.5
  text "18" at 4527.22,6437.5 h73.5
  text "18" at 9042.22,6432.5 h73.5
  text "18" at 2462.22,6427.5 h73.5
  text "6.000" at -1425,3575 h196
  text "17" at -7107.78,1627.5 h73.5
  text "18" at -6907.78,1627.5 h73.5
  text ".250" at -825,1625 h196
  text "17" at -6902.78,1442.5 h73.5
  text "0" at -1550,-100 h196
  text ".250" at 875,-400 h196
  text "11.000" at 5125,-825 h196
  text "18" at 3757.22,-1157.5 h73.5
  text "18" at 5232.22,-1172.5 h73.5
  text "18" at 9797.22,-1207.5 h73.5
  text "18" at 7907.22,-1217.5 h73.5
  text "0" at -75,-1400 h196
TOOLING_CORNERS:
  lines w8: -4,-4 -4,396 -4,-4 ; -4,-4 396,-4 -4,-4 ; -4,6004 396,6004 -4,6004 ; -4,6004 -4,5604 -4,6004 ; 11004,-4 10604,-4 11004,-4 ; 11004,-4 11004,396 11004,-4 ; 11004,6004 11004,5604 11004,6004 ; 11004,6004 10604,6004 11004,6004
  lines w35: -50,-50 -50,496 -50,-50 ; -50,-50 496,-50 -50,-50 ; -50,6050 496,6050 -50,6050 ; -50,6050 -50,5504 -50,6050 ; 11050,-50 10504,-50 11050,-50 ; 11050,-50 11050,496 11050,-50 ; 11050,6050 11050,5504 11050,6050 ; 11050,6050 10504,6050 11050,6050
TITLE_DATA:
  text "FABRICATION DRAWING" at 7625,-3560 h196
  text "1:1" at 7672,-4763 h152.88
TITLE_BLOCK:
  text "ASSEMBLY DRAWING" at 7625,-3560 h196
  text ".75:1" at 7560,-4765 h152.88
FAB_NOTES:
  drawing of 155 lines, arcs and shapes, not listed
  text "UNLESS OTHERWISE SPECIFIED:" at -7744,10423 h122.5
  text "1. USE ARTWORK MASTERS SUPPLIED." at -7744,10173 h98
  text "2. BOARD SHALL BE VERIFIED FOR COMPLIANCE WITH THE SUPPLIED IPC-D-356 NETLIST." at -7744,9973 h98
  text "3. DRAWING IS VIEWED FROM COMPONENT SIDE." at -7744,9773 h98
  text "4. ALL DIMENSIONS ARE IN INCHES." at -7744,9573 h98
  text "5. FINISHED BOARD SHALL MEET THE PERFORMANCE REQUIREMENTS OF IPC-6012 B, CLASS 2." at -7744,9373 h98
  text "6. MATERIAL:" at -7744,9173 h98
  text "BASE LAMINATE:  PLASTIC SHEET, GLASS BASE EPOXY RESIN, NEMA FR4" at -7744,8973 h98
  text "OR EQUIVALENT, UL94-V0." at -7744,8773 h98
  text "BONDING AGENT:  PREIMPREGNATED B-STAGE EPOXY GLASS CLOTH." at -7744,8573 h98
  text "7. BOARD BOW, WARP OR TWIST SHALL NOT EXCEED +/- 0.0075 PER INCH MEASURED" at -7744,8373 h98
  text "IN ACCORDANCE WITH IPC-TM-650, METHOD 2.4.22." at -7744,8173 h98
  text "8. HOLE SIZE SHALL BE PER HOLE LEGEND." at -7744,7973 h98
  text "9. DRILL BOARD USING DRILL DATA SUPPLIED. HOLE LOCATIONS MAY VARY" at -7744,7773 h98
  text "WITHIN 0.003 (RADIAL ERROR) MAX, ABOUT TRUE POSITION." at -7744,7573 h98
  text "10. REGISTRATION: FRONT TO BACK GRID REGISTRATION ON HOLE CENTERS" at -7744,7373 h98
  text "TO BE WITHIN 0.005." at -7744,7173 h98
  text "11. COPPER PLATE INDICATED HOLES, 0.001 MINIMUM WALL THICKNESS," at -7744,6973 h98
  text "12. TOTAL CIRCUIT ETCH ACROSS TRACES SHALL BE +/- 0.001 OF THE" at -7744,6773 h98
  text "SUPPLIED ARTWORK." at -7744,6573 h98
  text "13. SOLDER MASK OVER BARE COPPER BOTH SIDES USING LIQUID PHOTO-IMAGEABLE" at -7744,6373 h98
  text "SOLDERMASK PER IPC-SM-840." at -7744,6173 h98
  text "14. FINISH: SOLDER PLATE OVER EXPOSED CONDUCTORS, 0.0003 MIN THK," at -7744,5973 h98
  text "COMP SN60." at -7744,5773 h98
  text "15. SILKSCREEN BOTH SIDES WITH NONCONDUCTIVE CONTRASTING EPOXY INK" at -7744,5573 h98
  text "USING ARTWORK SUPPLIED." at -7744,5373 h98
  text "16. REMOVE ALL BURRS AND BREAK SHARP EDGES 0.015 INCH MAXIMUM." at -7744,5173 h98
  text "17. ALL 0.008 AND 0.010 VIA DRILLS (EXCEPT AS NOTED IN NOTE 18)" at -7744,4973 h98
  text "SHALL BE PLUGGED WITH LPI SOLDERMASK PRIOR TO APPLYING" at -7744,4773 h98
  text "THE COMPONENT AND SOLDER SIDE SOLDER MASKS." at -7744,4573 h98
  text "18. INDICATED VIAS SHALL BE COPPER FILLED." at -7744,4373 h98
  text "LAYER STACKUP" at -5480,-1820 h152.88
  text "COPPER WEIGHT SHOWN IS AFTER PLATING" at -6230,-2070 h98
  text "COMPONENT SIDE SILKSCREEN" at -3330,-2220 h78.4
  text "COMPONENT SIDE SOLDERMASK" at -3330,-2370 h78.4
  text "LAYER 1      COMPONENT SIDE         2.0 OZ" at -6430,-2545 h78.4
  text "0.063 +/-.010" at -7780,-2845 h78.4
  text "LAYER 2      GROUND PLANE           2.0 OZ" at -6430,-2845 h78.4
  text "INCLUDING" at -7580,-2995 h78.4
  text "FR-4 0.034" at -5180,-2995 h78.4
  text "SOLDERMASK" at -7605,-3145 h78.4
  text "LAYER 3      INTERNAL SIGNAL        2.0 OZ" at -6430,-3145 h78.4
  text "FR-4 0.008" at -5180,-3295 h78.4
  text "LAYER 4      SOLDER SIDE            2.0 OZ" at -6430,-3445 h78.4
  text "SOLDER SIDE SOLDERMASK" at -3330,-3620 h78.4
  text "SOLDER SIDE SILKSCREEN" at -3330,-3770 h78.4
LOGO:
  drawing of 294 lines, arcs and shapes, not listed
ASSYDWG:
  drawing of 4099 lines, arcs and shapes, not listed
  text "J2" at -5812.6,5635 h49
  text "J3" at -4312.6,5635 h49
  text "J4" at -2812.6,5635 h49
  text "J9" at -1322.6,5630 h49
  text "R18" at 294.87,5440 h49
  text "C102" at -5837.66,5400 h49
  text "C108" at -1342.66,5395 h49
  text "C103" at -4342.66,5390 h49
  text "C104" at -2837.66,5390 h49
  text "T3" at -6070.1,5366.2 h49
  text "T4" at -5545.1,5366.2 h49
  text "T5" at -4580.1,5361.2 h49
  text "T6" at -4055.1,5361.2 h49
  text "T7" at -3075.1,5361.2 h49
  text "T8" at -2550.1,5361.2 h49
  text "T18" at -1582.63,5356.2 h49
  text "T15" at -1057.63,5356.2 h49
  text "SW1" at 379.87,5280 h49
  text "R74" at 284.87,5150 h49
  text "ON" at 792.4,4880 h49
  text "1" at 588.64,4815 h49
  text "2" at 588.64,4740 h49
  text "C49" at -1265.13,4670 h49
  text "3" at 588.64,4665 h49
  text "C53" at 4738.67,4642.5 h49
  text "C48" at -1265.13,4605 h49
  text "4" at 588.64,4590 h49
  text "R42" at 4314.87,4590 h49
  text "C10" at -4425.13,4585 h49
  text "C16" at -2925.13,4585 h49
  text "C17" at -2765.13,4585 h49
  text "C141" at 7452.34,4585 h49
  text "C139" at 8957.34,4585 h49
  text "C140" at 9157.34,4585 h49
  text "C52" at 4738.67,4582.5 h49
  text "C4" at -5892.6,4580 h49
  text "C11" at -4255.13,4580 h49
  text "C144" at 5962.34,4580 h49
  text "C143" at 6167.34,4580 h49
  text "C142" at 7662.34,4580 h49
  text "C5" at -5772.6,4575 h49
  text "C47" at -1260.13,4540 h49
  text "C51" at 4314.87,4530 h49
  text "C50" at 4738.67,4522.5 h49
  text "SW3" at 369.87,4520 h49
  text "5" at 588.64,4515 h49
  text "C44" at -1105.13,4495 h49
  text "R44" at 4494.87,4490 h49
  text "1" at -1680.06,4485 h49
  text "R3" at -5657.6,4480 h49
  text "R6" at -4157.6,4480 h49
  text "R9" at -2657.6,4480 h49
  text "R39" at -1575.13,4470 h49
  text "C3" at -5987.6,4450 h49
  text "C15" at -3025.13,4450 h49
  text "C9" at -4482.6,4445 h49
  text "C133" at 6202.34,4445 h49
  text "C132" at 7707.34,4445 h49
  text "6" at 588.64,4440 h49
  text "C134" at 9207.34,4440 h49
  text "C45" at -1085.13,4430 h49
  text "R36" at 4369.87,4425 h49
  text "U1" at -5702.6,4420 h49
  text "U3" at -2692.6,4415 h49
  text "U2" at -4187.6,4410 h49
  text "R54" at 5119.87,4410 h49
  text "U7" at -1457.6,4395 h49
  text "R4" at 7697.4,4370 h49
  text "R1" at 9207.4,4370 h49
  text "7" at 588.64,4365 h49
  text "R7" at 6202.4,4365 h49
  text "C43" at -1055.13,4345 h49
  text "J17" at -1820.13,4335 h49
  text "C42" at 4729.87,4330 h49
  text "R31" at 5119.87,4330 h49
  text "C38" at -1455.13,4315 h49
  text "8" at 588.64,4290 h49
  text "C40" at 4428.67,4290 h49
  text "C1" at -5882.6,4270 h49
  text "C2" at -5782.6,4270 h49
  text "C8" at -4392.6,4270 h49
  text "C7" at -4277.6,4270 h49
  text "C14" at -2925.13,4270 h49
  text "C13" at -2765.13,4270 h49
  text "C39" at -1450.13,4250 h49
  text "R27" at -1190.13,4250 h49
  text "C41" at 4428.67,4233.7 h49
  text "T1" at -6947.6,4210 h49
  text "3" at -1685.06,4180 h49
  text "1" at 531.14,4082.5 h49
  text "2" at 643.64,4082.5 h49
  text "R73" at 366.57,3875.2 h49
  text "PG8" at 109.91,3872.5 h37.24
  text "R63" at 3874.91,3840 h37.24
  text "R72" at 366.57,3819 h49
  text "PG7" at 109.91,3816.2 h37.24
  text "C101" at -6420,3807.66 h49 r270
  text "R62" at 3874.91,3795 h37.24
  text "POWER MICRO BOARD REV" at -2952.75,3792.7 h73.5
  text "J1" at -6862.6,3770 h49
  text "U11" at -30.13,3765 h49
  text "C151" at 3257.34,3765 h49
  text "U10" at 3605,3765.13 h49 r270
  text "R71" at 366.57,3762.7 h49
  text "PG6" at 109.91,3760 h37.24
  text "R61" at 3874.91,3745 h37.24
  text "R70" at 366.57,3706.5 h49
  text "PG5" at 109.91,3703.7 h37.24
  text "R60" at 3874.91,3700 h37.24
  text "J13" at 779.87,3665 h49
  text "R59" at 3874.91,3655 h37.24
  text "R69" at 366.57,3650.2 h49
  text "PG4" at 109.91,3647.5 h37.24
  text "R58" at 3874.91,3605 h37.24
  text "S/N" at -3082.3,3595.2 h73.5
  text "R68" at 366.57,3594 h49
  text "PG3" at 109.91,3591.2 h37.24
  text "uPOL" at -4137.85,3590.2 h147
  text "R57" at 3874.91,3560 h37.24
  text "R67" at 366.57,3537.7 h49
  text "PG2" at 109.91,3535 h37.24
  text "R56" at 3874.91,3515 h37.24
  text "R66" at 366.57,3481.5 h49
  text "R65" at 3580,3480.13 h49 r270
  text "R64" at 3645,3480.13 h49 r270
  text "PG1" at 109.91,3478.7 h37.24
  text "C128" at 3450,3472.66 h49 r270
  text "C129" at 3520,3472.66 h49 r270
  text "C130" at 3715,3472.66 h49 r270
  text "T2" at -6947.6,3325 h49
  text "C138" at -6420,3287.66 h49 r270
  text "19" at 503.6,3262.5 h49
  text "20" at 616.1,3262.5 h49
  text "C113" at 4683.64,3121.2 h49
  text "R45" at -1465.13,3100 h49
  text "C111" at -1187.66,3095 h49
  text "U9" at 3531.2,3088.7 h49
  text "J18" at -6990.13,3085 h49
  text "C20" at -5890.13,3085 h49
  text "C19" at -5705.13,3085 h49
  text "C26" at -4385.13,3080 h49
  text "C25" at -4210.13,3080 h49
  text "C28" at -2710.13,3080 h49
  text "C27" at -2885.13,3075 h49
  text "C112" at 4683.64,3065 h49
  text "1" at 3474.74,3049 h49
  text "3" at 3611.94,3049 h49
  text "C110" at -1187.66,3030 h49
  text "C115" at -1637.66,3025 h49
  text "C114" at 4332.34,3015 h49
  text "D15" at -6735,3000.13 h49 r270
  text "V1" at -6480,2992.6 h49 r270
  text "R75" at 319.87,2980 h49
  text "R21" at 7594.87,2980 h49
  text "R10" at 9089.87,2980 h49
  text "R22" at 6094.87,2975 h49
  text "U8" at -1167.6,2960 h49
  text "U4" at -5937.6,2955 h49
  text "U6" at -2932.6,2955 h49
  text "U5" at -4432.6,2945 h49
  text "R50" at 4729.87,2935 h49
  text "C116" at -1607.66,2930 h49
  text "C29" at -4125.13,2910 h49
  text "C136" at 6097.34,2910 h49
  text "C137" at 7592.34,2910 h49
  text "C135" at 9102.34,2910 h49
  text "C21" at -5630.13,2905 h49
  text "C30" at -2625.13,2905 h49
  text "R51" at -1070.13,2885 h49
  text "C131" at 3307.34,2885 h49
  text "R12" at -6015.13,2880 h49
  text "R23" at -4500.13,2880 h49
  text "R24" at -3005.13,2880 h49
  text "C125" at 3717.34,2880 h49
  text "R53" at 4604.87,2865 h49
  text "3" at -910.06,2860 h49
  text "C117" at -1587.66,2855 h49
  text "SW2" at 369.87,2840 h49
  text "C122" at 4327.34,2840 h49
  text "C121" at 4802.34,2825 h49
  text "C126" at 3297.34,2805 h49
  text "C118" at -1123.96,2801.2 h49
  text "C23" at -5885.13,2775 h49
  text "C33" at -4395.13,2775 h49
  text "C34" at -2885.13,2775 h49
  text "C22" at -5730.13,2770 h49
  text "C31" at -4235.13,2770 h49
  text "C32" at -2730.13,2770 h49
  text "C123" at 4327.34,2770 h49
  text "C149" at 5927.34,2770 h49
  text "C150" at 6127.34,2770 h49
  text "C146" at 8922.34,2770 h49
  text "C145" at 9127.34,2770 h49
  text "C148" at 7422.34,2765 h49
  text "C147" at 7632.34,2765 h49
  text "R52" at 4794.87,2760 h49
  text "C119" at -1123.96,2745 h49
  text "R46" at 3984.87,2730 h49
  text "R55" at 314.87,2720 h49
  text "J14" at -830.13,2715 h49
  text "C124" at 4322.34,2700 h49
  text "C120" at -1123.96,2688.7 h49
  text "R38" at 3984.87,2640 h49
  text "1" at -910.06,2550 h49
  text "R76" at 784.87,2380 h49
  text "J21" at 419.87,2355 h49
  text "R77" at 784.87,2315 h49
  text "J19" at 414.87,2270 h49
  text "R78" at 784.87,2250 h49
  text "J20" at 414.87,2190 h49
  text "3" at 624.94,2115 h49
  text "T11" at -4602.63,2001.2 h49
  text "T10" at -4077.63,2001.2 h49
  text "T13" at -3087.63,1991.2 h49
  text "T12" at -2562.63,1991.2 h49
  text "T9" at -6080.1,1986.2 h49
  text "T14" at -5567.63,1986.2 h49
  text "T17" at -1592.63,1986.2 h49
  text "T16" at -1067.63,1986.2 h49
  text "R47" at 801.87,1968.5 h49
  text "C105" at -4342.66,1965 h49
  text "C107" at -2842.66,1965 h49
  text "C106" at -5847.66,1960 h49
  text "C109" at -1337.66,1960 h49
  text "J11" at 489.87,1960 h49
  text "R48" at 801.87,1893.5 h49
  text "1" at 629.94,1810 h49
  text "J8" at -1317.6,1725 h49
  text "J5" at -5812.6,1720 h49
  text "J6" at -4322.6,1720 h49
  text "J7" at -2807.6,1715 h49
  text "ASSEMBLY TOP VIEW" at -4444.41,870 h196
  text "ASSEMBLY BOTTOM VIEW" at 4513.19,770 h196
MODULES:
  text "CR_1_2" at 3901.6,3922.8 h24.5
  text "CR_1_3" at 5901.6,3922 h24.5
  text "CR_2_1" at 7710.5,3890.3 h24.5
  text "CR_1_2" at 3797,3833.3 h24.5
  text "CR_1_3" at 5819.4,3833.3 h24.5
  text "CR_1_1" at 1690,3677 h24.5
  text "CR_2_1" at 7577,3638.3 h24.5
  text "CR_1_4" at 1901.6,1922 h24.5
  text "CR_1_5" at 3901.6,1922 h24.5
  text "CR_1_5" at 3826.6,1902 h24.5
  text "CR_1_6" at 5798,1838.3 h24.5
  text "CR_1_4" at 1819.4,1833.3 h24.5
  text "CR_1_5" at 3819.4,1833.3 h24.5
  text "CR_1_6" at 5797,1833.3 h24.5
  text "CR_2_2" at 7562,1643.3 h24.5
DISPLAY_BOTTOM:
  text "ASSEMBLY DRAWING REAR" at 3269,-675 h73.5
DISPLAY_TOP:
  text "ASSEMBLY DRAWING" at 3269,-675 h73.5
